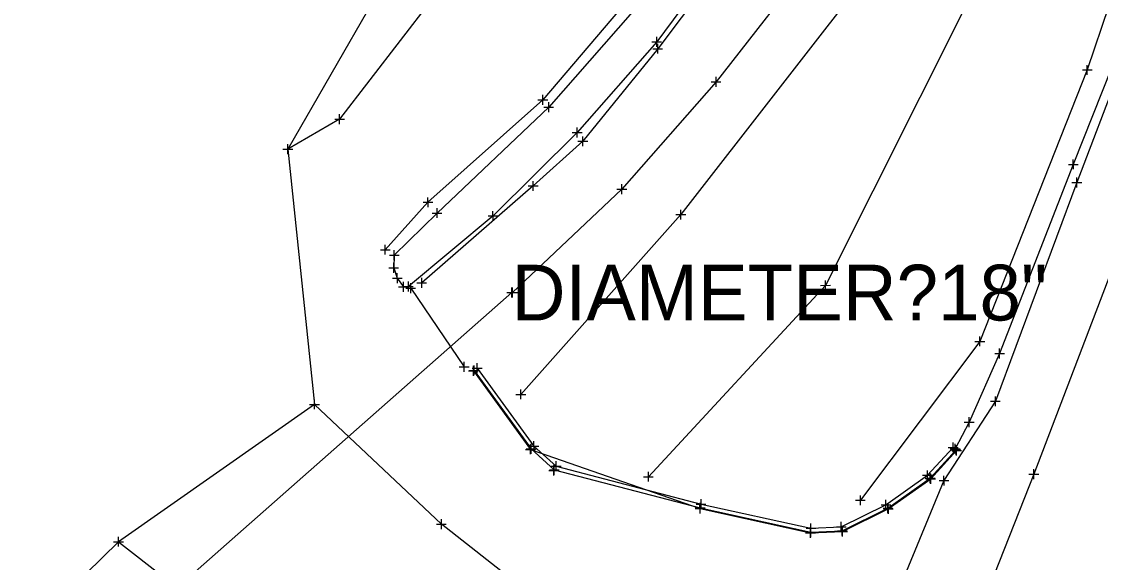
# Model space of a CAD drawing. Extents: x -1 to 1157254, y -1 to 2021979.
# Drawn here: x 1151479.8 to 1151619.2, y 2019275.4 to 2019345.3 of the extents above; entities that cross this region are included whole.
import ezdxf

# ---------------------------------------------------------------- set-up
doc = ezdxf.new("R2010")
doc.units = 0
for name, color, linetype in [('S_BUILDING_ANNOT', 7, 'Continuous'), ('S_CTL_TABLE', 7, 'Continuous'), ('S_DRIVEWAY_ANNOT', 7, 'Continuous'), ('S_DROP_INLET_ANNOT', 7, 'Continuous'), ('S_EDGE_BITUMINOUS_ANNOT', 7, 'Continuous'), ('S_EDGE_CONCRETE', 7, 'Continuous'), ('S_EDGE_CONCRETE_ANNOT', 7, 'Continuous'), ('S_EDGE_PAVEMENT', 7, 'Continuous'), ('S_ENV_CONSTRAINT', 7, 'Continuous'), ('S_EXISTING_ALIGNMENT_ANNOT', 7, 'Continuous'), ('S_FLAG_POLE', 7, 'Continuous'), ('S_GAS_PUMP_ISLAND_ANNOT', 7, 'Continuous')]:
    doc.layers.add(name, color=color, linetype=linetype)

msp = doc.modelspace()

# ---------------------------------------------------------------- linework, layer by layer
at = {"layer": 'S_BUILDING_ANNOT'}
for p, q in [((1151561.26, 2019342.64), (1151562.54, 2019342.65)), ((1151561.9, 2019342.01), (1151561.9, 2019343.28)), ((1151561.9, 2019342.64), (1151561.9, 2019342.64)), ((1151569.57, 2019336.83), (1151569.57, 2019338.11)), ((1151568.93, 2019337.47), (1151570.21, 2019337.47)), ((1151569.57, 2019337.47), (1151569.57, 2019337.47)), ((1151547.31, 2019334.2), (1151548.58, 2019334.2)), ((1151547.95, 2019333.56), (1151547.94, 2019334.83)), ((1151547.95, 2019334.2), (1151547.95, 2019334.2)), ((1151551.62, 2019330.28), (1151551.62, 2019331.55)), ((1151550.99, 2019330.91), (1151552.26, 2019330.92)), ((1151551.62, 2019330.91), (1151551.62, 2019330.91)), ((1151615.75, 2019326.16), (1151615.74, 2019327.43)), ((1151615.11, 2019326.8), (1151616.38, 2019326.8)), ((1151615.74, 2019326.8), (1151615.74, 2019326.8)), ((1151557.39, 2019322.95), (1151557.38, 2019324.23)), ((1151615.56, 2019324.46), (1151616.83, 2019324.47)), ((1151616.19, 2019323.83), (1151616.19, 2019325.1)), ((1151616.19, 2019324.46), (1151616.19, 2019324.46)), ((1151556.75, 2019323.59), (1151558.02, 2019323.59)), ((1151557.38, 2019323.59), (1151557.38, 2019323.59)), ((1151532.87, 2019320.51), (1151534.15, 2019320.51)), ((1151533.51, 2019319.88), (1151533.51, 2019321.15)), ((1151533.51, 2019320.51), (1151533.51, 2019320.51)), ((1151540.11, 2019320.13), (1151541.38, 2019320.14)), ((1151540.75, 2019319.5), (1151540.74, 2019320.77)), ((1151540.75, 2019320.14), (1151540.75, 2019320.14)), ((1151527.35, 2019315.08), (1151528.62, 2019315.08)), ((1151527.99, 2019314.44), (1151527.98, 2019315.72)), ((1151527.99, 2019315.08), (1151527.99, 2019315.08)), ((1151527.28, 2019313.42), (1151528.55, 2019313.42)), ((1151527.92, 2019312.79), (1151527.92, 2019314.06)), ((1151527.92, 2019313.42), (1151527.92, 2019313.42)), ((1151527.75, 2019312.08), (1151529.02, 2019312.08)), ((1151528.39, 2019311.44), (1151528.38, 2019312.72)), ((1151528.38, 2019312.08), (1151528.38, 2019312.08)), ((1151529.17, 2019310.33), (1151529.16, 2019311.61)), ((1151529.82, 2019310.39), (1151529.82, 2019311.66)), ((1151528.53, 2019310.97), (1151529.8, 2019310.97)), ((1151529.17, 2019310.97), (1151529.17, 2019310.97)), ((1151529.18, 2019311.02), (1151530.45, 2019311.03)), ((1151529.48, 2019310.79), (1151530.75, 2019310.79)), ((1151529.82, 2019311.02), (1151529.82, 2019311.02)), ((1151530.12, 2019310.15), (1151530.12, 2019311.43)), ((1151530.12, 2019310.79), (1151530.12, 2019310.79)), ((1151542.52, 2019310.23), (1151543.8, 2019310.23)), ((1151542.62, 2019310.23), (1151543.9, 2019310.23)), ((1151543.16, 2019309.6), (1151543.16, 2019310.87)), ((1151543.16, 2019310.23), (1151543.16, 2019310.23)), ((1151543.26, 2019309.6), (1151543.26, 2019310.87)), ((1151543.26, 2019310.23), (1151543.26, 2019310.23)), ((1151605.59, 2019302.36), (1151606.86, 2019302.36)), ((1151606.22, 2019301.72), (1151606.22, 2019303)), ((1151606.22, 2019302.36), (1151606.22, 2019302.36)), ((1151536.38, 2019300.65), (1151537.65, 2019300.65)), ((1151537.02, 2019300.01), (1151537.02, 2019301.29)), ((1151537.02, 2019300.65), (1151537.02, 2019300.65)), ((1151538.07, 2019300.48), (1151539.34, 2019300.48)), ((1151538.22, 2019299.49), (1151538.22, 2019300.76)), ((1151538.3, 2019299.55), (1151538.3, 2019300.82)), ((1151538.7, 2019299.84), (1151538.7, 2019301.11)), ((1151538.7, 2019300.48), (1151538.7, 2019300.48)), ((1151537.58, 2019300.13), (1151538.85, 2019300.13)), ((1151537.66, 2019300.18), (1151538.94, 2019300.19)), ((1151538.22, 2019300.13), (1151538.22, 2019300.13)), ((1151538.3, 2019300.18), (1151538.3, 2019300.18)), ((1151517.69, 2019295.16), (1151517.69, 2019296.43)), ((1151605.67, 2019295.55), (1151605.67, 2019296.82)), ((1151517.05, 2019295.79), (1151518.33, 2019295.79)), ((1151517.69, 2019295.79), (1151517.69, 2019295.79)), ((1151605.03, 2019296.18), (1151606.3, 2019296.18)), ((1151605.67, 2019296.18), (1151605.67, 2019296.18)), ((1151601.65, 2019293.49), (1151602.92, 2019293.49)), ((1151602.28, 2019292.85), (1151602.28, 2019294.13)), ((1151602.28, 2019293.49), (1151602.28, 2019293.49)), ((1151546.05, 2019289.74), (1151546.04, 2019291.01)), ((1151600.22, 2019289.59), (1151600.21, 2019290.86)), ((1151600.48, 2019289.42), (1151600.48, 2019290.69)), ((1151544.96, 2019289.97), (1151546.23, 2019289.97)), ((1151545.03, 2019290.03), (1151546.31, 2019290.04)), ((1151545.41, 2019290.37), (1151546.68, 2019290.37)), ((1151545.6, 2019289.33), (1151545.59, 2019290.61)), ((1151545.6, 2019289.97), (1151545.6, 2019289.97)), ((1151545.67, 2019289.4), (1151545.67, 2019290.67)), ((1151545.67, 2019290.04), (1151545.67, 2019290.04)), ((1151546.04, 2019290.37), (1151546.04, 2019290.37)), ((1151599.58, 2019290.22), (1151600.85, 2019290.23)), ((1151599.84, 2019290.05), (1151601.12, 2019290.06)), ((1151599.95, 2019289.89), (1151601.22, 2019289.89)), ((1151600.02, 2019289.82), (1151601.29, 2019289.82)), ((1151600.22, 2019290.23), (1151600.22, 2019290.23)), ((1151600.48, 2019290.06), (1151600.48, 2019290.06)), ((1151600.59, 2019289.25), (1151600.58, 2019290.52)), ((1151600.58, 2019289.89), (1151600.58, 2019289.89)), ((1151600.66, 2019289.18), (1151600.66, 2019290.46)), ((1151600.66, 2019289.82), (1151600.66, 2019289.82)), ((1151548.67, 2019286.7), (1151548.67, 2019287.98)), ((1151548.91, 2019287.16), (1151548.91, 2019288.43)), ((1151547.98, 2019287.25), (1151549.25, 2019287.25)), ((1151548.03, 2019287.34), (1151549.3, 2019287.34)), ((1151548.28, 2019287.79), (1151549.55, 2019287.79)), ((1151548.62, 2019286.61), (1151548.62, 2019287.89)), ((1151548.62, 2019287.25), (1151548.62, 2019287.25)), ((1151548.67, 2019287.34), (1151548.67, 2019287.34)), ((1151548.91, 2019287.79), (1151548.91, 2019287.79)), ((1151596.27, 2019286.62), (1151597.54, 2019286.62)), ((1151596.91, 2019285.98), (1151596.91, 2019287.25)), ((1151596.91, 2019286.62), (1151596.91, 2019286.62)), ((1151597.24, 2019285.6), (1151597.24, 2019286.88)), ((1151597.31, 2019285.53), (1151597.31, 2019286.8)), ((1151599.03, 2019285.3), (1151599.02, 2019286.57)), ((1151610.01, 2019286.76), (1151611.28, 2019286.77)), ((1151610.65, 2019286.13), (1151610.64, 2019287.4)), ((1151610.64, 2019286.76), (1151610.64, 2019286.76)), ((1151596.6, 2019286.24), (1151597.88, 2019286.24)), ((1151596.67, 2019286.16), (1151597.94, 2019286.17)), ((1151597.24, 2019286.24), (1151597.24, 2019286.24)), ((1151597.31, 2019286.16), (1151597.31, 2019286.16)), ((1151598.39, 2019285.94), (1151599.66, 2019285.94)), ((1151599.02, 2019285.94), (1151599.02, 2019285.94)), ((1151566.86, 2019282.32), (1151568.13, 2019282.32)), ((1151566.88, 2019282.41), (1151568.15, 2019282.42)), ((1151567, 2019282.9), (1151568.27, 2019282.9)), ((1151567.5, 2019281.68), (1151567.49, 2019282.96)), ((1151567.5, 2019282.32), (1151567.5, 2019282.32)), ((1151567.52, 2019281.78), (1151567.52, 2019283.05)), ((1151567.52, 2019282.42), (1151567.52, 2019282.42)), ((1151567.64, 2019282.27), (1151567.63, 2019283.54)), ((1151567.64, 2019282.9), (1151567.64, 2019282.9)), ((1151590.89, 2019282.79), (1151592.16, 2019282.79)), ((1151591.15, 2019282.36), (1151592.42, 2019282.36)), ((1151591.53, 2019282.15), (1151591.52, 2019283.43)), ((1151591.53, 2019282.79), (1151591.53, 2019282.79)), ((1151591.78, 2019281.72), (1151591.78, 2019283)), ((1151591.78, 2019282.36), (1151591.78, 2019282.36)), ((1151591.84, 2019281.64), (1151591.83, 2019282.91)), ((1151534.08, 2019279.68), (1151534.07, 2019280.95)), ((1151591.2, 2019282.27), (1151592.47, 2019282.28)), ((1151591.83, 2019282.27), (1151591.83, 2019282.27)), ((1151533.44, 2019280.32), (1151534.71, 2019280.32)), ((1151534.08, 2019280.32), (1151534.08, 2019280.32)), ((1151581.2, 2019279.78), (1151582.47, 2019279.78)), ((1151581.8, 2019278.64), (1151581.79, 2019279.91)), ((1151581.79, 2019278.54), (1151581.79, 2019279.81)), ((1151581.84, 2019279.14), (1151581.84, 2019280.41)), ((1151581.84, 2019279.78), (1151581.84, 2019279.78)), ((1151585.12, 2019279.96), (1151586.39, 2019279.96)), ((1151585.76, 2019279.32), (1151585.75, 2019280.6)), ((1151585.76, 2019279.96), (1151585.76, 2019279.96)), ((1151585.88, 2019278.83), (1151585.88, 2019280.1)), ((1151585.91, 2019278.73), (1151585.91, 2019280)), ((1151492.35, 2019277.4), (1151492.35, 2019278.67)), ((1151581.15, 2019279.17), (1151582.42, 2019279.18)), ((1151581.16, 2019279.27), (1151582.43, 2019279.28)), ((1151581.79, 2019279.18), (1151581.79, 2019279.18)), ((1151581.8, 2019279.28), (1151581.8, 2019279.28)), ((1151585.25, 2019279.46), (1151586.52, 2019279.47)), ((1151585.27, 2019279.36), (1151586.54, 2019279.37)), ((1151585.88, 2019279.46), (1151585.88, 2019279.46)), ((1151585.91, 2019279.37), (1151585.91, 2019279.37)), ((1151491.71, 2019278.03), (1151492.99, 2019278.04)), ((1151492.35, 2019278.03), (1151492.35, 2019278.03))]:
    msp.add_line(p, q, dxfattribs=at)
at = {"layer": 'S_CTL_TABLE'}
for p, q in [((1151562.03, 2019341.12), (1151562.03, 2019342.39)), ((1151561.39, 2019341.75), (1151562.67, 2019341.75)), ((1151562.03, 2019341.75), (1151562.03, 2019341.75)), ((1151617.54, 2019338.37), (1151617.54, 2019339.64)), ((1151616.91, 2019339), (1151618.18, 2019339.01)), ((1151617.54, 2019339), (1151617.54, 2019339)), ((1151547.2, 2019334.5), (1151547.2, 2019335.77)), ((1151546.56, 2019335.14), (1151547.84, 2019335.14)), ((1151547.2, 2019335.14), (1151547.2, 2019335.14)), ((1151520.29, 2019332.63), (1151521.56, 2019332.64)), ((1151520.93, 2019332), (1151520.92, 2019333.27)), ((1151520.93, 2019332.63), (1151520.93, 2019332.63)), ((1151551.72, 2019329.79), (1151552.99, 2019329.79)), ((1151552.36, 2019329.15), (1151552.36, 2019330.42)), ((1151552.36, 2019329.79), (1151552.36, 2019329.79)), ((1151513.6, 2019328.78), (1151514.88, 2019328.78)), ((1151514.24, 2019328.14), (1151514.24, 2019329.42)), ((1151514.24, 2019328.78), (1151514.24, 2019328.78)), ((1151545.95, 2019323.37), (1151545.94, 2019324.65)), ((1151545.31, 2019324.01), (1151546.58, 2019324.01)), ((1151545.95, 2019324.01), (1151545.95, 2019324.01)), ((1151531.71, 2019321.9), (1151532.98, 2019321.91)), ((1151532.35, 2019321.27), (1151532.34, 2019322.54)), ((1151532.34, 2019321.91), (1151532.34, 2019321.91)), ((1151564.39, 2019320.31), (1151565.66, 2019320.31)), ((1151565.03, 2019319.67), (1151565.02, 2019320.94)), ((1151565.02, 2019320.31), (1151565.02, 2019320.31)), ((1151526.82, 2019315.14), (1151526.82, 2019316.41)), ((1151526.19, 2019315.77), (1151527.46, 2019315.77)), ((1151526.82, 2019315.77), (1151526.82, 2019315.77)), ((1151531.53, 2019310.85), (1151531.53, 2019312.13)), ((1151583.7, 2019310.53), (1151583.7, 2019311.8)), ((1151530.9, 2019311.49), (1151532.17, 2019311.49)), ((1151531.53, 2019311.49), (1151531.53, 2019311.49)), ((1151583.07, 2019311.16), (1151584.34, 2019311.17)), ((1151583.7, 2019311.16), (1151583.7, 2019311.16)), ((1151603.02, 2019303.92), (1151604.29, 2019303.92)), ((1151603.65, 2019303.29), (1151603.65, 2019304.56)), ((1151603.65, 2019303.92), (1151603.65, 2019303.92)), ((1151544.34, 2019296.44), (1151544.33, 2019297.71)), ((1151543.7, 2019297.07), (1151544.97, 2019297.08)), ((1151544.34, 2019297.08), (1151544.34, 2019297.08)), ((1151560.83, 2019285.8), (1151560.83, 2019287.08)), ((1151560.19, 2019286.44), (1151561.46, 2019286.44)), ((1151560.83, 2019286.44), (1151560.83, 2019286.44)), ((1151588.23, 2019282.76), (1151588.22, 2019284.03)), ((1151587.59, 2019283.39), (1151588.86, 2019283.4)), ((1151588.23, 2019283.39), (1151588.23, 2019283.39))]:
    msp.add_line(p, q, dxfattribs=at)
at = {"layer": 'S_DRIVEWAY_ANNOT'}
msp.add_lwpolyline([(1151651.47, 2019520.49), (1151648.35, 2019494.94), (1151642.93, 2019453.01), (1151634.35, 2019451.64), (1151626.09, 2019427.17), (1151620.59, 2019413.48), (1151609.61, 2019393.71), (1151597.12, 2019376.77), (1151583, 2019354.65), (1151569.57, 2019337.47), (1151557.38, 2019323.59), (1151543.26, 2019310.23)], dxfattribs=at)
at = {"layer": 'S_DROP_INLET_ANNOT'}
msp.add_lwpolyline([(1151543.16, 2019310.23), (1151497.9, 2019270.32)], dxfattribs=at)
at = {"layer": 'S_EDGE_BITUMINOUS_ANNOT'}
for points in [[(1151619.15, 2019642.05), (1151612.56, 2019585.86), (1151610.26, 2019549.54), (1151602.56, 2019524.71), (1151599.8, 2019498.43), (1151592.22, 2019474.55), (1151588.1, 2019456.36), (1151576.42, 2019434.24), (1151568.91, 2019417.02), (1151560.41, 2019402.93), (1151553.39, 2019388.72), (1151536.45, 2019367.4), (1151532.69, 2019347.87), (1151520.93, 2019332.63), (1151514.24, 2019328.78)], [(1151656.97, 2019640.74), (1151652.85, 2019578.69), (1151645.47, 2019542.24), (1151639.62, 2019515.83), (1151632.61, 2019488.58), (1151624.44, 2019462.62), (1151617.83, 2019444.2), (1151605.65, 2019419.87), (1151596.45, 2019403), (1151587.54, 2019388.09), (1151575.57, 2019371.06), (1151559.08, 2019349.14), (1151547.2, 2019335.14), (1151532.34, 2019321.91), (1151526.82, 2019315.77)], [(1151661.79, 2019619.06), (1151660.51, 2019587.98), (1151656.76, 2019562.88), (1151650.81, 2019536.28), (1151647.92, 2019522.04), (1151642.18, 2019499.13), (1151630.81, 2019461.03), (1151624.49, 2019442.97), (1151616.61, 2019425.86), (1151614.55, 2019421.37), (1151612.72, 2019418.75), (1151602.4, 2019400.52), (1151594.84, 2019386.81), (1151591.39, 2019381.53), (1151577.01, 2019361.63), (1151562.03, 2019341.75), (1151552.36, 2019329.79), (1151545.95, 2019324.01), (1151531.53, 2019311.49)], [(1151638.98, 2019443.81), (1151629.61, 2019425.39), (1151616.29, 2019398.6), (1151590.7, 2019353.34), (1151565.02, 2019320.31), (1151544.34, 2019297.08)], [(1151646.3, 2019439.81), (1151638.96, 2019421.77), (1151622.93, 2019393.79), (1151602.01, 2019347.62), (1151583.7, 2019311.16), (1151560.83, 2019286.44)], [(1151634.32, 2019388.68), (1151617.54, 2019339), (1151603.65, 2019303.92), (1151588.23, 2019283.39)]]:
    msp.add_lwpolyline(points, dxfattribs=at)
at = {"layer": 'S_EDGE_CONCRETE'}
msp.add_lwpolyline([(1151665.32, 2019618.35), (1151663.56, 2019588.8), (1151659.6, 2019534.06), (1151659.4, 2019525.74), (1151657.28, 2019494.5), (1151654.81, 2019454.84), (1151653.17, 2019443.85), (1151648.96, 2019412.39), (1151646.72, 2019396.58), (1151641.51, 2019373.7), (1151635.32, 2019351.87), (1151623.96, 2019321.63), (1151610.64, 2019286.76), (1151594.67, 2019246.27), (1151580.05, 2019209.17), (1151567.29, 2019174.79), (1151552.07, 2019136.21), (1151533.12, 2019087.68), (1151518.11, 2019049.1), (1151500.76, 2019006.34), (1151490.98, 2018988.8), (1151485.56, 2018980.44)], dxfattribs=at)
at = {"layer": 'S_EDGE_CONCRETE_ANNOT'}
msp.add_lwpolyline([(1151582.55, 2019251.27), (1151566.37, 2019259.17), (1151550.26, 2019267.59), (1151534.08, 2019280.32), (1151517.69, 2019295.79)], dxfattribs=at)
at = {"layer": 'S_EDGE_PAVEMENT'}
for points in [[(1151678.47, 2019913.2), (1151677.32, 2019893.25), (1151674.5, 2019848.21), (1151671.66, 2019784.4), (1151670.47, 2019748.35), (1151668.33, 2019693.33), (1151666.31, 2019657.65), (1151663.78, 2019619.32), (1151661.98, 2019588.03), (1151660.12, 2019562.72), (1151658.24, 2019535.25), (1151657.78, 2019525.86), (1151655.58, 2019494.48), (1151653.12, 2019454.64), (1151651.07, 2019450.93), (1151638.9, 2019407.22), (1151634.97, 2019387.23), (1151628.88, 2019364.3), (1151623.2, 2019345.64), (1151615.74, 2019326.8), (1151606.22, 2019302.36), (1151602.28, 2019293.49), (1151600.48, 2019290.06)], [(1151538.7, 2019300.48), (1151546.04, 2019290.37), (1151548.91, 2019287.79), (1151567.64, 2019282.9), (1151581.84, 2019279.78), (1151585.76, 2019279.96), (1151591.53, 2019282.79), (1151596.91, 2019286.62), (1151600.22, 2019290.23)], [(1151538.3, 2019300.18), (1151545.67, 2019290.04), (1151548.67, 2019287.34), (1151567.52, 2019282.42), (1151581.8, 2019279.28), (1151585.88, 2019279.46), (1151591.78, 2019282.36), (1151597.24, 2019286.24), (1151600.58, 2019289.89)]]:
    msp.add_lwpolyline(points, dxfattribs=at)
at = {"layer": 'S_ENV_CONSTRAINT'}
for points in [[(1151530.12, 2019310.79), (1151537.02, 2019300.65)], [(1151538.22, 2019300.13), (1151545.6, 2019289.97), (1151567.5, 2019282.32), (1151581.79, 2019279.18), (1151585.91, 2019279.37), (1151591.83, 2019282.27), (1151597.31, 2019286.16), (1151600.66, 2019289.82)], [(1151492.35, 2019278.03), (1151504.81, 2019268.34)]]:
    msp.add_lwpolyline(points, dxfattribs=at)
at = {"layer": 'S_EXISTING_ALIGNMENT_ANNOT'}
for points in [[(1151658, 2019640.31), (1151654.6, 2019578.39), (1151646.72, 2019541.42), (1151640.83, 2019515.22), (1151633.46, 2019488.44), (1151625.73, 2019462.45), (1151618.86, 2019443.11), (1151606.96, 2019418.98), (1151597.48, 2019402.17), (1151588.83, 2019387.16), (1151576.55, 2019370.06), (1151560.33, 2019348.3), (1151547.95, 2019334.2), (1151533.51, 2019320.51), (1151527.99, 2019315.08), (1151527.92, 2019313.42), (1151528.38, 2019312.08), (1151529.17, 2019310.97)], [(1151660.79, 2019605.72), (1151659.91, 2019584.82), (1151659.22, 2019579.66), (1151657.63, 2019570.15), (1151649.05, 2019531.68), (1151642.71, 2019504.31), (1151635.48, 2019479.5), (1151629.99, 2019461.49), (1151623.84, 2019443.45), (1151615.96, 2019426.27), (1151609.16, 2019413.45), (1151602.06, 2019400.9), (1151593.39, 2019385.82), (1151590.46, 2019381.17), (1151576.55, 2019362.41), (1151561.9, 2019342.64), (1151551.62, 2019330.91), (1151540.75, 2019320.14), (1151529.82, 2019311.02)]]:
    msp.add_lwpolyline(points, dxfattribs=at)
at = {"layer": 'S_FLAG_POLE'}
msp.add_lwpolyline([(1151651.74, 2019446.21), (1151642.73, 2019420.11), (1151639.07, 2019399.11), (1151633.8, 2019377.52), (1151627.31, 2019353.6), (1151616.19, 2019324.46), (1151605.67, 2019296.18), (1151599.02, 2019285.94), (1151584.12, 2019249.83), (1151584.02, 2019249.78), (1151575.24, 2019228.32), (1151565.98, 2019203.98), (1151563.23, 2019187.26), (1151551.04, 2019156.21), (1151544.92, 2019141), (1151525.15, 2019091.21), (1151509.97, 2019051.62), (1151493.39, 2019009.53), (1151485.44, 2018993.67), (1151485.4, 2018993.91), (1151479.82, 2018984.3)], dxfattribs=at)
at = {"layer": 'S_GAS_PUMP_ISLAND_ANNOT'}
msp.add_lwpolyline([(1151614.49, 2019602.33), (1151613.33, 2019592.4), (1151612.56, 2019585.86), (1151611.93, 2019575.88), (1151604.33, 2019530.44), (1151602.56, 2019524.71), (1151593.74, 2019479.37), (1151592.22, 2019474.55), (1151576.42, 2019434.24), (1151560.41, 2019402.93), (1151536.45, 2019367.4), (1151514.24, 2019328.78), (1151517.69, 2019295.79), (1151492.35, 2019278.03), (1151481.88, 2019267.77)], dxfattribs=at)

# ---------------------------------------------------------------- texts
at = {"layer": 'S_BUILDING_ANNOT'}
msp.add_text('DIAMETER?18"', height=7.2, dxfattribs=at).set_placement((1151543.16, 2019306.63))

doc.saveas('drawing.dxf')
